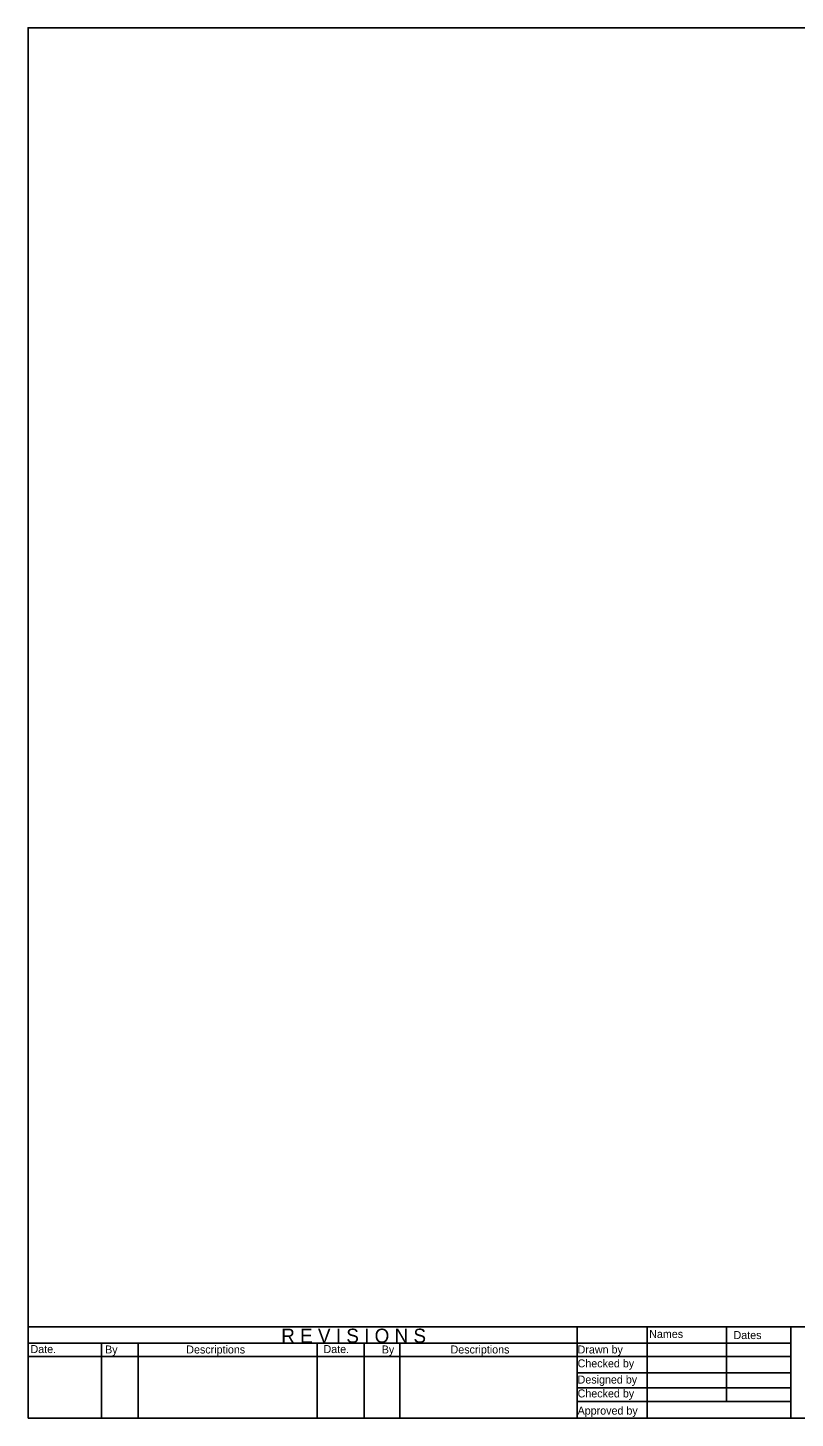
# Model space of a CAD drawing. Extents: x 0.6 to 16.4, y 0.2 to 10.3.
# Drawn here: x 0.57 to 6.16, y 0.16 to 10.29 of the extents above; entities that cross this region are included whole.
import ezdxf

# ---------------------------------------------------------------- set-up
doc = ezdxf.new("R2010")
doc.units = 0
for name, color, linetype in [('Level 23', 7, 'Continuous'), ('Level 46', 7, 'Continuous'), ('Level 63', 7, 'Continuous')]:
    doc.layers.add(name, color=color, linetype=linetype)

msp = doc.modelspace()

# ---------------------------------------------------------------- linework, layer by layer
at = {"layer": 'Level 23'}
for p, q in [((4.572, 0.161), (4.572, 0.827)), ((4.572, 0.161), (4.572, 0.827)), ((5.083, 0.161), (5.083, 0.827)), ((5.083, 0.161), (5.083, 0.827)), ((5.083, 0.161), (5.083, 0.827)), ((5.661, 0.282), (5.661, 0.827)), ((5.661, 0.282), (5.661, 0.827)), ((6.128, 0.161), (6.128, 0.827)), ((6.128, 0.161), (6.128, 0.827)), ((6.128, 0.161), (6.128, 0.827)), ((6.128, 0.161), (6.128, 0.827)), ((0.576, 0.707), (6.128, 0.707)), ((0.576, 0.707), (6.128, 0.707)), ((0.576, 0.611), (4.851, 0.611)), ((0.576, 0.611), (4.851, 0.611)), ((1.111, 0.161), (1.111, 0.707)), ((1.111, 0.161), (1.111, 0.707)), ((1.378, 0.161), (1.378, 0.707)), ((1.378, 0.161), (1.378, 0.707)), ((2.679, 0.161), (2.679, 0.707)), ((2.679, 0.161), (2.679, 0.707)), ((3.021, 0.161), (3.021, 0.707)), ((3.021, 0.161), (3.021, 0.707)), ((3.281, 0.161), (3.281, 0.707)), ((3.281, 0.161), (3.281, 0.707)), ((4.851, 0.611), (6.128, 0.611)), ((4.851, 0.611), (6.128, 0.611)), ((4.572, 0.492), (6.128, 0.492)), ((4.572, 0.492), (6.128, 0.492)), ((4.572, 0.383), (6.128, 0.383)), ((4.572, 0.383), (6.128, 0.383)), ((4.572, 0.282), (6.128, 0.282)), ((4.572, 0.282), (6.128, 0.282)), ((0.575, 0.161), (16.447, 0.161))]:
    msp.add_line(p, q, dxfattribs=at)
at = {"layer": 'Level 46'}
msp.add_line((0.573, 0.827), (16.447, 0.827), dxfattribs=at)
msp.add_line((0.573, 0.827), (16.447, 0.827), dxfattribs=at)
at = {"layer": 'Level 63'}
msp.add_lwpolyline([(0.575, 0.161), (16.447, 0.161), (16.447, 10.287), (0.575, 10.287), (0.575, 0.161)], dxfattribs=at)

# ---------------------------------------------------------------- texts
at = {"layer": 'Level 23'}
for s, height, p in [('R E V I S I O N S', 0.10284, (2.418, 0.71)), ('Names', 0.0583, (5.097, 0.745)), ('Dates', 0.0583, (5.711, 0.737)), ('Date.', 0.0583, (0.593, 0.635)), ('By', 0.0583, (1.136, 0.632)), ('Descriptions', 0.05827, (1.727, 0.632)), ('Date.', 0.0583, (2.726, 0.635)), ('By', 0.0583, (3.15, 0.632)), ('Descriptions', 0.05827, (3.651, 0.632)), ('Drawn by', 0.0583, (4.576, 0.632)), ('Checked by', 0.0583, (4.576, 0.531)), ('Designed by', 0.05827, (4.576, 0.413)), ('Checked by', 0.0583, (4.576, 0.312)), ('Approved by', 0.05827, (4.576, 0.187))]:
    msp.add_text(s, height=height, dxfattribs=at).set_placement(p)

doc.saveas('drawing.dxf')
